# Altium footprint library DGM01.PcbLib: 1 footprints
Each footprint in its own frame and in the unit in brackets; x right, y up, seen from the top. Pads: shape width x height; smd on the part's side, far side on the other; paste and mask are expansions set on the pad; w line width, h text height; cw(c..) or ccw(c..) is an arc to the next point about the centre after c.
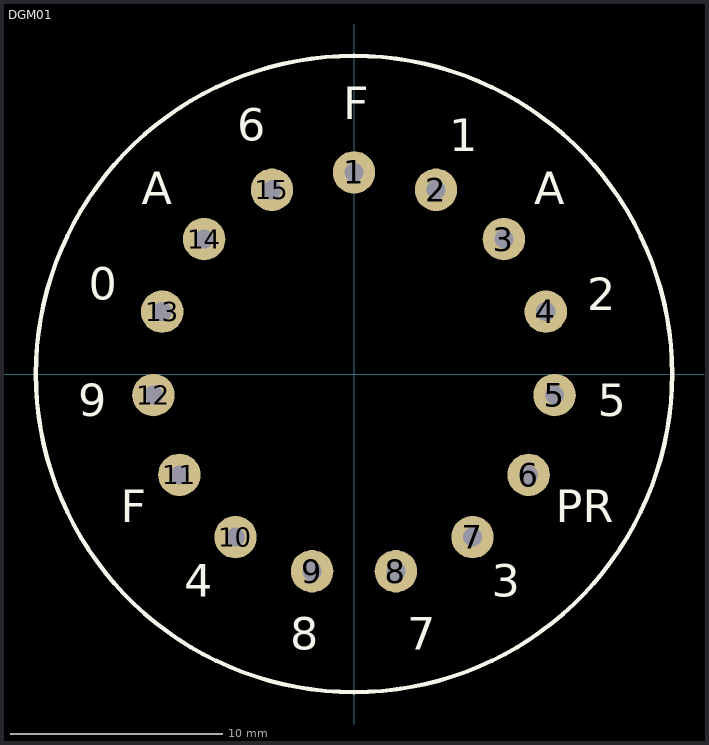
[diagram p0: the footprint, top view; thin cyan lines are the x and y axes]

## DGM01 [mm] "DGM01 socket"
pads (15):
  round 2 hole 0.9: 1(0,9.506) 2(3.867,8.685) 3(7.065,6.361) 4(9.041,2.938) 5(9.454,-0.994) 6(8.233,-4.753) 7(5.588,-7.691) 8(1.977,-9.299) 9(-1.977,-9.299) 10(-5.588,-7.691) 11(-8.233,-4.753) 12(-9.454,-0.994) 13(-9.041,2.938) 14(-7.065,6.361) 15(-3.867,8.685)
Top Overlay:
  circle w0.2: c0,0 r15
  text "6" at -5.5,11 h1.52
  text "A" at -10,8 h1.52
  text "0" at -12.5,3.5 h1.52
  text "9" at -13,-2 h1.52
  text "F" at -11,-7 h1.52
  text "4" at -8,-10.5 h1.52
  text "8" at -3,-13 h1.52
  text "7" at 2.5,-13 h1.52
  text "3" at 6.5,-10.5 h1.52
  text "PR" at 9.5,-7 h1.52
  text "5" at 11.5,-2 h1.52
  text "2" at 11,3 h1.52
  text "A" at 8.5,8 h1.52
  text "1" at 4.5,10.5 h1.52
  text "F" at -0.5,12 h1.52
